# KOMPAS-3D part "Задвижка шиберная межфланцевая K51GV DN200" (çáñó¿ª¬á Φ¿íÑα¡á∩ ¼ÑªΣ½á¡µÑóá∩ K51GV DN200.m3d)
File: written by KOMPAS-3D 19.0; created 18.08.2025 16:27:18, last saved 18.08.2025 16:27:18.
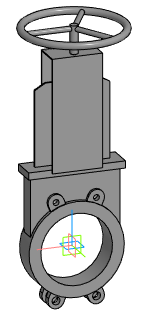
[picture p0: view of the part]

Document properties: Автор: Евгений; Полное имя файла: E:\Dendor Работа Сачек\3D для проектировщиков\2.4 Тип K51GV. Задвижка шиберная межфланцевая\stp_Задвижка шиберная K51GV DN50-400 с маховиком\Задвижка шиберная межфланцевая K51GV DN200.m3d

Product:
- Part/product: Задвижка шиберная межфланцевая K51GV DN200

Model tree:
1. Операция без истории:1  (labels: Задвижка шиберная межфланцевая K51GV DN200)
